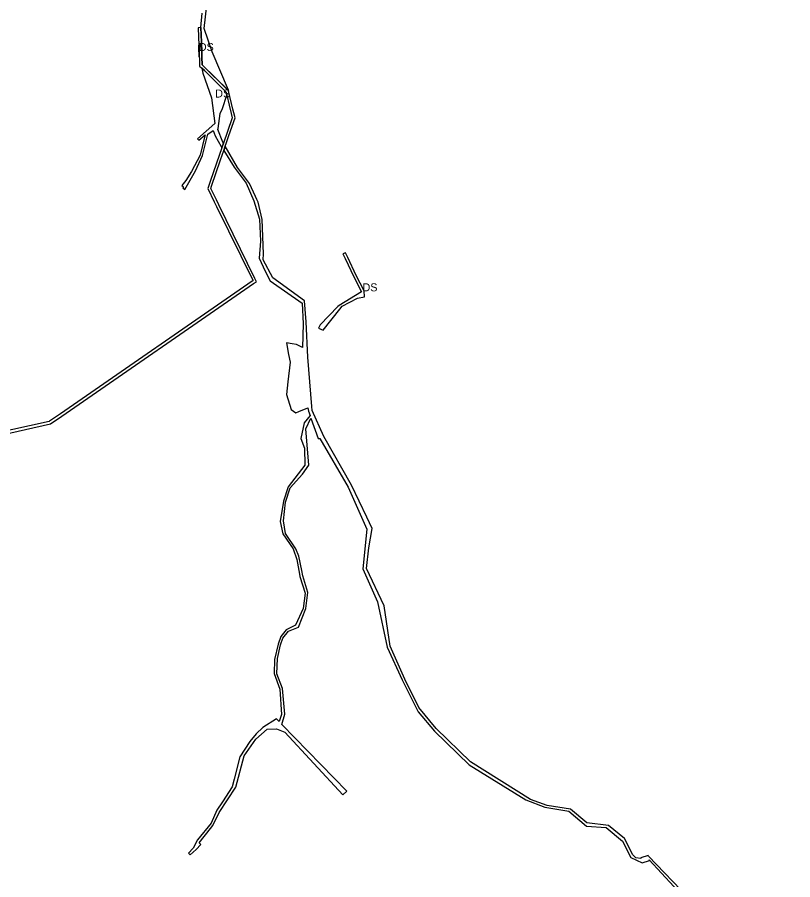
# Model space of a CAD drawing. Extents: x -477304 to -465641, y -1159113 to -1149285.
# Drawn here: x -472433 to -471561, y -1157281 to -1156311 of the extents above; entities that cross this region are included whole.
import ezdxf

# ---------------------------------------------------------------- set-up
doc = ezdxf.new("R2010")
doc.units = 0
doc.layers.add('35', color=7, linetype='Continuous')
doc.layers.add('4', color=7, linetype='Continuous')

msp = doc.modelspace()

# ---------------------------------------------------------------- linework, layer by layer
at = {"layer": '35'}
for p, q in [((-472225.92, -1156306.34), (-472227.48, -1156322.58)), ((-472229.2, -1156342.24), (-472229.67, -1156348.42)), ((-472229.67, -1156348.42), (-472228.7, -1156355.42)), ((-472228.7, -1156355.42), (-472229.2, -1156342.24)), ((-472222.92, -1156370.84), (-472225.92, -1156367.97)), ((-472195.94, -1156393.37), (-472195.83, -1156393.03)), ((-472195.83, -1156393.03), (-472195.83, -1156393.03)), ((-472215.11, -1156401.45), (-472211.38, -1156430.27)), ((-472211.38, -1156430.27), (-472230.73, -1156447.46)), ((-472219.04, -1156442.5), (-472213.09, -1156438.13)), ((-472213.09, -1156438.13), (-472210.91, -1156444.09)), ((-472202.34, -1156451.13), (-472207.73, -1156437.16)), ((-472230.73, -1156447.46), (-472229.38, -1156449.05)), ((-472229.38, -1156449.05), (-472222.02, -1156442.93)), ((-472225.09, -1156466.21), (-472219.04, -1156442.5)), ((-472210.91, -1156444.09), (-472204.29, -1156456)), ((-472204.29, -1156456), (-472203.29, -1156457.58)), ((-472203.29, -1156457.58), (-472201.53, -1156452.5)), ((-472201.53, -1156452.5), (-472202.34, -1156451.13)), ((-472199.54, -1156455.9), (-472201.24, -1156460.83)), ((-472185.57, -1156479.67), (-472199.54, -1156455.9)), ((-472227.54, -1156465.77), (-472237.61, -1156484.28)), ((-472233.11, -1156483.49), (-472225.09, -1156466.21)), ((-472201.24, -1156460.83), (-472189.45, -1156479.5)), ((-472244.92, -1156504.42), (-472233.11, -1156483.49)), ((-472189.45, -1156479.5), (-472175.9, -1156497.52)), ((-472172.34, -1156497.78), (-472185.57, -1156479.67)), ((-472247.38, -1156502.55), (-472244.92, -1156504.42)), ((-472165.57, -1156512.48), (-472172.34, -1156497.78)), ((-472164.03, -1156515.81), (-472165.57, -1156512.48)), ((-472162.63, -1156518.86), (-472164.03, -1156515.81)), ((-472161.36, -1156581.78), (-472154.69, -1156596.46)), ((-472156.82, -1156583.75), (-472156.59, -1156576.94)), ((-472145.9, -1156603.72), (-472156.82, -1156583.75)), ((-472064.45, -1156575.57), (-472067.29, -1156576.79)), ((-472067.29, -1156576.79), (-472066.88, -1156577.62)), ((-472066.88, -1156577.62), (-472064.73, -1156581.94)), ((-472110.56, -1156629.77), (-472145.9, -1156603.72)), ((-472046.46, -1156619.66), (-472071.48, -1156635.09)), ((-472113.15, -1156632.23), (-472111.91, -1156655.48)), ((-472073.01, -1156636.03), (-472092.8, -1156656.83)), ((-472071.48, -1156635.09), (-472073.01, -1156636.03)), ((-472111.91, -1156655.48), (-472112.58, -1156682.28)), ((-472092.8, -1156656.83), (-472094.72, -1156660.51)), ((-472094.72, -1156660.51), (-472089.53, -1156662.5)), ((-472124.43, -1156678.1), (-472130.56, -1156677.02)), ((-472130.56, -1156677.02), (-472128.26, -1156690.13)), ((-472119.49, -1156678.96), (-472124.43, -1156678.1)), ((-472112.58, -1156682.28), (-472119.49, -1156678.96)), ((-472102.13, -1156748.38), (-472106.6, -1156693.17)), ((-472129.2, -1156720.58), (-472130.45, -1156734.89)), ((-472130.45, -1156734.89), (-472125.45, -1156752.02)), ((-472101.66, -1156752.84), (-472102.13, -1156748.38)), ((-472125.45, -1156752.02), (-472120.23, -1156755.51)), ((-472120.23, -1156755.51), (-472116.85, -1156754.18)), ((-472116.85, -1156754.18), (-472106.65, -1156750.16)), ((-472104.17, -1156758.45), (-472110.92, -1156766.84)), ((-472106.65, -1156750.16), (-472105.77, -1156753.91)), ((-472105.77, -1156753.91), (-472104.17, -1156758.45)), ((-472112.69, -1156824.65), (-472105.67, -1156814.35)), ((-472040.39, -1156872.85), (-472057.38, -1156837.01)), ((-472133.84, -1156854.82), (-472137.65, -1156877.79)), ((-472131.9, -1156891.12), (-472134.18, -1156877.11)), ((-472115.64, -1156939.74), (-472109.66, -1156958.42)), ((-472109.66, -1156958.42), (-472111.98, -1156975.72)), ((-472117.22, -1156996.68), (-472108.79, -1156975.73)), ((-472014.15, -1157017.88), (-472020.76, -1156972.6)), ((-472144.52, -1157048.8), (-472138.07, -1157066.42)), ((-472135.04, -1157065.47), (-472141.34, -1157049.12)), ((-472138.07, -1157066.42), (-472136.41, -1157094.86)), ((-472132.33, -1157094.42), (-472135.04, -1157065.47)), ((-472136.41, -1157094.86), (-472138.86, -1157102.74)), ((-472135.82, -1157105.92), (-472132.33, -1157094.42)), ((-471982.49, -1157091.95), (-471964.09, -1157113.59)), ((-472141.73, -1157099.61), (-472157.18, -1157109.25)), ((-472138.86, -1157102.74), (-472141.73, -1157099.61)), ((-472062.73, -1157181.13), (-472135.82, -1157105.92)), ((-472141.79, -1157111.03), (-472138.11, -1157112.42)), ((-472138.11, -1157112.42), (-472132.67, -1157114.74)), ((-472132.67, -1157114.74), (-472067.45, -1157184.91)), ((-471964.09, -1157113.59), (-471925.24, -1157151.43)), ((-471923.67, -1157147.83), (-471962.37, -1157110.62)), ((-471856.14, -1157190.27), (-471923.67, -1157147.83)), ((-472067.45, -1157184.91), (-472062.73, -1157181.13)), ((-471837.36, -1157196.96), (-471856.14, -1157190.27)), ((-471811.21, -1157201.13), (-471837.36, -1157196.96)), ((-471813.06, -1157203.36), (-471793.31, -1157220.43)), ((-471792.79, -1157216.73), (-471811.21, -1157201.13)), ((-472215.48, -1157216.89), (-472230.85, -1157235.79)), ((-472228.76, -1157239.18), (-472216.06, -1157222.93)), ((-472230.85, -1157235.79), (-472235.67, -1157245.18)), ((-472232.19, -1157246.54), (-472227.02, -1157240.88)), ((-472227.02, -1157240.88), (-472228.76, -1157239.18)), ((-471740.99, -1157252.54), (-471750.7, -1157234.33)), ((-472235.67, -1157245.18), (-472240.99, -1157250.68)), ((-472240.99, -1157250.68), (-472238.82, -1157252.7)), ((-472238.82, -1157252.7), (-472232.19, -1157246.54)), ((-471737.77, -1157255.76), (-471740.99, -1157252.54)), ((-471723.89, -1157253.32), (-471732.21, -1157255.8)), ((-471723.65, -1157254), (-471723.89, -1157253.32)), ((-471731.99, -1157256.49), (-471737.77, -1157255.76)), ((-471732.21, -1157255.8), (-471731.99, -1157256.49)), ((-471730.75, -1157261.38), (-471722.41, -1157258.89)), ((-471722.41, -1157258.89), (-471722.6, -1157258.15))]:
    msp.add_line(p, q, dxfattribs=at)
for points in [[(-472195.83, -1156393.03), (-472195.78, -1156392.87), (-472214.25, -1156349.85), (-472223.08, -1156323.37), (-472220, -1156293.97), (-472221.11, -1156282.75), (-472225.31, -1156269.61), (-472231.1, -1156257.62)], [(-472227.48, -1156322.58), (-472226.95, -1156322.56), (-472226.32, -1156338.94), (-472225.88, -1156350.61), (-472225.68, -1156355.75), (-472225.36, -1156364.36), (-472195.94, -1156393.37)], [(-472225.92, -1156367.97), (-472224.58, -1156373.7), (-472215.11, -1156401.45)], [(-472197.63, -1156398.52), (-472198.42, -1156395.16), (-472222.92, -1156370.84)], [(-472205.22, -1156419.01), (-472202.46, -1156413.31), (-472197.63, -1156398.52)], [(-472207.73, -1156437.16), (-472207.57, -1156436.02), (-472205.22, -1156419.01)], [(-472222.02, -1156442.93), (-472222.3, -1156444.11), (-472227.54, -1156465.77)], [(-472237.61, -1156484.28), (-472243.98, -1156494.24), (-472248.43, -1156500.15), (-472246.59, -1156501.57), (-472247.38, -1156502.55)], [(-472175.9, -1156497.52), (-472167.27, -1156517.41), (-472161.1, -1156537.76)], [(-472156.59, -1156576.94), (-472158.07, -1156538.16), (-472162.63, -1156518.86)], [(-472161.1, -1156537.76), (-472159.97, -1156562.54), (-472161.36, -1156581.78)], [(-472064.73, -1156581.94), (-472054.9, -1156602.89), (-472046.46, -1156619.66)], [(-472052.13, -1156601.31), (-472061.77, -1156581.16), (-472064.45, -1156575.57)], [(-472154.69, -1156596.46), (-472148.86, -1156607.26), (-472113.15, -1156632.23)], [(-472068.01, -1156635.7), (-472050.64, -1156626.67), (-472043.04, -1156625.37), (-472043.4, -1156618.57), (-472052.13, -1156601.31)], [(-472106.6, -1156693.17), (-472108.48, -1156653.16), (-472110.56, -1156629.77)], [(-472089.53, -1156662.5), (-472070.79, -1156639.17), (-472068.01, -1156635.7)], [(-472128.26, -1156690.13), (-472126.68, -1156698.62), (-472129.2, -1156720.58)], [(-472057.38, -1156837.01), (-472088.59, -1156782.23), (-472101.66, -1156752.84)], [(-472110.92, -1156766.84), (-472114.67, -1156784.55), (-472110.56, -1156795.45)], [(-472105.67, -1156814.35), (-472109.01, -1156773.78), (-472103.09, -1156761.52)], [(-472103.09, -1156761.52), (-472094.92, -1156784.65), (-472093.22, -1156784.34), (-472061.29, -1156839.12)], [(-472110.56, -1156795.45), (-472110.02, -1156814.3), (-472128.66, -1156838.67), (-472133.84, -1156854.82)], [(-472134.18, -1156877.11), (-472131.62, -1156856.16), (-472126.34, -1156839.84), (-472112.69, -1156824.65)], [(-472061.29, -1156839.12), (-472040.15, -1156886.39), (-472044.67, -1156931.16)], [(-472038.08, -1156907.56), (-472034.3, -1156885.69), (-472040.39, -1156872.85)], [(-472137.65, -1156877.79), (-472134.67, -1156891.58), (-472123.24, -1156908.61), (-472119.06, -1156920.54)], [(-472113.51, -1156932.89), (-472116.84, -1156916.62), (-472120.14, -1156908.39), (-472131.9, -1156891.12)], [(-472020.76, -1156972.6), (-472040.64, -1156930.59), (-472038.08, -1156907.56)], [(-472119.06, -1156920.54), (-472116.1, -1156937.17), (-472115.64, -1156939.74)], [(-472108.79, -1156975.73), (-472106.65, -1156957.43), (-472112.25, -1156939.06), (-472113.51, -1156932.89)], [(-472044.67, -1156931.16), (-472028.48, -1156968.14), (-472017.4, -1157018.9), (-472000.47, -1157055.81), (-471982.49, -1157091.95)], [(-472111.98, -1156975.72), (-472120.66, -1156994.46), (-472130.93, -1156999.52), (-472136.92, -1157007.17)], [(-472134.74, -1157008.79), (-472128.22, -1157001.2), (-472117.22, -1156996.68)], [(-472136.92, -1157007.17), (-472140.19, -1157015.85), (-472144.26, -1157033.09), (-472144.52, -1157048.8)], [(-472141.34, -1157049.12), (-472140.73, -1157032), (-472137.22, -1157016.42), (-472134.74, -1157008.79)], [(-471962.37, -1157110.62), (-471981.89, -1157086.77), (-471997.39, -1157055.21), (-472014.15, -1157017.88)], [(-472206.25, -1157204.92), (-472187.64, -1157176.63), (-472178.42, -1157141.34), (-472165.12, -1157122.56), (-472152.48, -1157111.16), (-472141.79, -1157111.03)], [(-472157.18, -1157109.25), (-472164.83, -1157116.37), (-472171.84, -1157125.31)], [(-472171.84, -1157125.31), (-472182.96, -1157142.41), (-472189.4, -1157167.4)], [(-471925.24, -1157151.43), (-471861.66, -1157190.58), (-471840.27, -1157199.12), (-471813.06, -1157203.36)], [(-472189.4, -1157167.4), (-472191.71, -1157176.15), (-472202.77, -1157193.05)], [(-472202.77, -1157193.05), (-472208.93, -1157202.48), (-472215.48, -1157216.89)], [(-472216.06, -1157222.93), (-472213.55, -1157219.72), (-472206.25, -1157204.92)], [(-471793.31, -1157220.43), (-471770.99, -1157221.99), (-471752.92, -1157237.27)], [(-471750.7, -1157234.33), (-471768.52, -1157219.42), (-471792.79, -1157216.73)], [(-471752.92, -1157237.27), (-471743.41, -1157255.45), (-471730.75, -1157261.38)], [(-471641.71, -1157318.3), (-471678.13, -1157301.12), (-471723.65, -1157254)], [(-471722.6, -1157258.15), (-471681.2, -1157303.19), (-471643.9, -1157320.4), (-471590.29, -1157350.68), (-471577.28, -1157359.79), (-471561.3, -1157365.18)]]:
    msp.add_lwpolyline(points, dxfattribs=at)
at = {"layer": '4'}
msp.add_lwpolyline([(-472460.91, -1156782.48), (-472395.88, -1156767.93), (-472395.88, -1156767.93), (-472395.88, -1156767.93), (-472383.48, -1156759.37), (-472167.68, -1156610.33), (-472164.52, -1156608.15), (-472166.2, -1156604.71), (-472206.74, -1156521.94), (-472209.51, -1156516.27), (-472215.91, -1156503.22), (-472215.07, -1156500.81), (-472204.86, -1156471.28), (-472201.24, -1156460.83), (-472199.54, -1156455.9), (-472198.11, -1156451.78), (-472196.54, -1156447.25), (-472195.36, -1156443.83), (-472188.54, -1156424.13), (-472189.87, -1156418.44), (-472190.86, -1156414.24), (-472195.7, -1156393.61), (-472225.36, -1156364.36), (-472225.68, -1156355.75), (-472225.88, -1156350.61), (-472226.32, -1156338.94), (-472226.95, -1156322.56), (-472227.48, -1156322.58), (-472229.94, -1156322.68), (-472229.55, -1156333.05), (-472229.2, -1156342.24), (-472228.7, -1156355.42), (-472228.63, -1156357.24), (-472228.31, -1156365.69), (-472225.92, -1156367.97), (-472222.92, -1156370.84), (-472198.42, -1156395.16), (-472197.63, -1156398.52), (-472195.02, -1156409.63), (-472192.84, -1156418.93), (-472191.66, -1156423.96), (-472196.99, -1156439.36), (-472198.5, -1156443.74), (-472199.94, -1156447.89), (-472201.53, -1156452.5), (-472203.29, -1156457.58), (-472206.34, -1156466.38), (-472216.06, -1156494.48), (-472219.15, -1156503.42), (-472211.85, -1156518.32), (-472209.25, -1156523.62), (-472168.67, -1156606.49), (-472168.35, -1156607.15), (-472169.06, -1156607.64), (-472384.95, -1156756.74), (-472397.1, -1156765.13), (-472397.41, -1156765.2), (-472460.91, -1156779.41)], dxfattribs=at)

# ---------------------------------------------------------------- texts
at = {"layer": '35'}
for p in [(-472229.18, -1156348.83), (-472210.75, -1156401.11), (-472045.07, -1156619.03)]:
    msp.add_text('DS', height=9, dxfattribs=at).set_placement(p)

doc.saveas('drawing.dxf')
